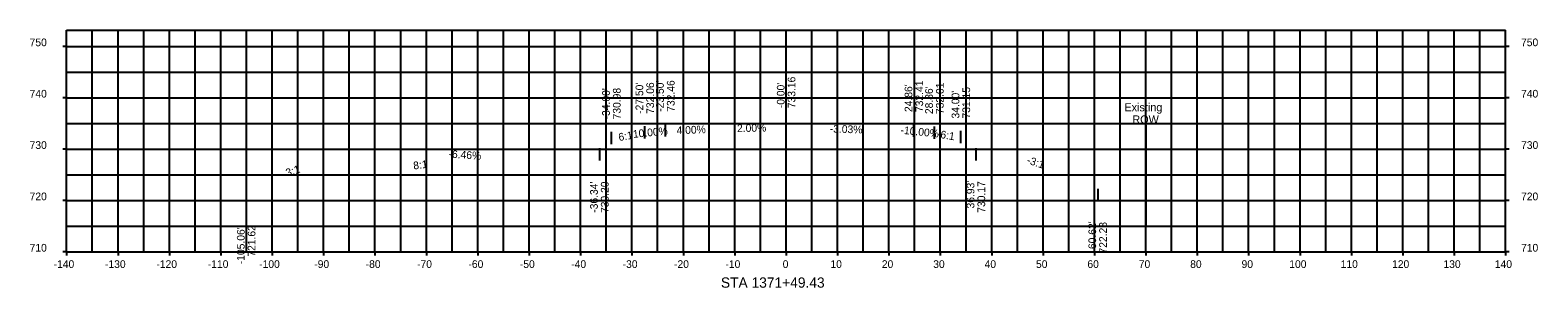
# Model space of a CAD drawing. Extents: x -147 to 146, y 703 to 753.
import ezdxf

# ---------------------------------------------------------------- set-up
doc = ezdxf.new("R2010")
doc.units = 0
for name, color, linetype in [('CorridorGraphics', 7, 'Continuous'), ('Text', 7, 'Continuous'), ('TL_DNC', 7, 'Continuous'), ('TL_PavementBtm', 7, 'Continuous'), ('TL_Set', 7, 'Continuous'), ('TL_SubbaseBtm', 7, 'Continuous')]:
    doc.layers.add(name, color=color, linetype=linetype)

msp = doc.modelspace()

# ---------------------------------------------------------------- linework, layer by layer
at = {"layer": 'CorridorGraphics'}
for p, q in [((-140, 753.16), (140, 753.16)), ((-140, 710), (-140, 753.16)), ((140, 710), (140, 753.16)), ((-140, 710), (140, 710))]:
    msp.add_line(p, q, dxfattribs=at)
at = {"layer": 'TL_DNC'}
for p, q in [((-135, 710), (-135, 753.16)), ((-125, 710), (-125, 753.16)), ((-115, 710), (-115, 753.16)), ((-105, 710), (-105, 753.16)), ((-95, 710), (-95, 753.16)), ((-85, 710), (-85, 753.16)), ((-75, 710), (-75, 753.16)), ((-65, 710), (-65, 753.16)), ((-55, 710), (-55, 753.16)), ((-45, 710), (-45, 753.16)), ((-35, 710), (-35, 753.16)), ((-25, 710), (-25, 753.16)), ((-15, 710), (-15, 753.16)), ((-5, 710), (-5, 753.16)), ((5, 710), (5, 753.16)), ((15, 710), (15, 753.16)), ((25, 710), (25, 753.16)), ((35, 710), (35, 753.16)), ((45, 710), (45, 753.16)), ((55, 710), (55, 753.16)), ((65, 710), (65, 753.16)), ((75, 710), (75, 753.16)), ((85, 710), (85, 753.16)), ((95, 710), (95, 753.16)), ((105, 710), (105, 753.16)), ((115, 710), (115, 753.16)), ((125, 710), (125, 753.16)), ((135, 710), (135, 753.16)), ((-140, 745), (140, 745)), ((-140, 735), (140, 735)), ((-140, 725), (140, 725)), ((-140, 715), (140, 715))]:
    msp.add_line(p, q, dxfattribs=at)
at = {"layer": 'TL_PavementBtm'}
for p, q in [((-27.5, 732.06), (-27.5, 734.46)), ((-23.5, 732.46), (-23.5, 734.86)), ((0, 733.16), (0, 735.56)), ((24.86, 732.41), (24.86, 734.81)), ((24.86, 732.41), (24.86, 734.81)), ((28.86, 732.01), (28.86, 734.41)), ((34, 731.15), (34, 733.55)), ((-34, 730.98), (-34, 733.38)), ((-36.34, 730.2), (-36.34, 727.8)), ((36.93, 730.17), (36.93, 727.77)), ((60.62, 722.28), (60.62, 719.88)), ((-105.06, 721.62), (-105.06, 719.22))]:
    msp.add_line(p, q, dxfattribs=at)
at = {"layer": 'TL_Set'}
msp.add_line((70.01, 734.64), (70.01, 714.95), dxfattribs=at)
at = {"layer": 'TL_SubbaseBtm'}
for p, q in [((-140, 710), (-140, 753.16)), ((-130, 710), (-130, 753.16)), ((-120, 710), (-120, 753.16)), ((-110, 710), (-110, 753.16)), ((-100, 710), (-100, 753.16)), ((-90, 710), (-90, 753.16)), ((-80, 710), (-80, 753.16)), ((-70, 710), (-70, 753.16)), ((-60, 710), (-60, 753.16)), ((-50, 710), (-50, 753.16)), ((-40, 710), (-40, 753.16)), ((-30, 710), (-30, 753.16)), ((-20, 710), (-20, 753.16)), ((-10, 710), (-10, 753.16)), ((0, 710), (0, 753.16)), ((10, 710), (10, 753.16)), ((20, 710), (20, 753.16)), ((30, 710), (30, 753.16)), ((40, 710), (40, 753.16)), ((50, 710), (50, 753.16)), ((60, 710), (60, 753.16)), ((70, 710), (70, 753.16)), ((80, 710), (80, 753.16)), ((90, 710), (90, 753.16)), ((100, 710), (100, 753.16)), ((110, 710), (110, 753.16)), ((120, 710), (120, 753.16)), ((130, 710), (130, 753.16)), ((140, 710), (140, 753.16)), ((-140, 750), (-140.72, 750)), ((-140, 750), (140, 750)), ((140.72, 750), (140, 750)), ((-140, 740), (-140.72, 740)), ((-140, 740), (140, 740)), ((140.72, 740), (140, 740)), ((-140, 730), (-140.72, 730)), ((-140, 730), (140, 730)), ((140.72, 730), (140, 730)), ((-140, 720), (-140.72, 720)), ((-140, 720), (140, 720)), ((140.72, 720), (140, 720)), ((-140, 710), (-140.72, 710)), ((-140, 710), (-140, 709.28)), ((-130, 710), (-130, 709.28)), ((-120, 710), (-120, 709.28)), ((-110, 710), (-110, 709.28)), ((-100, 710), (-100, 709.28)), ((-90, 710), (-90, 709.28)), ((-80, 710), (-80, 709.28)), ((-70, 710), (-70, 709.28)), ((-60, 710), (-60, 709.28)), ((-50, 710), (-50, 709.28)), ((-40, 710), (-40, 709.28)), ((-30, 710), (-30, 709.28)), ((-20, 710), (-20, 709.28)), ((-10, 710), (-10, 709.28)), ((0, 710), (0, 709.28)), ((10, 710), (10, 709.28)), ((20, 710), (20, 709.28)), ((30, 710), (30, 709.28)), ((40, 710), (40, 709.28)), ((50, 710), (50, 709.28)), ((60, 710), (60, 709.28)), ((70, 710), (70, 709.28)), ((80, 710), (80, 709.28)), ((90, 710), (90, 709.28)), ((100, 710), (100, 709.28)), ((110, 710), (110, 709.28)), ((120, 710), (120, 709.28)), ((130, 710), (130, 709.28)), ((140, 710), (140, 709.28)), ((140.72, 710), (140, 710))]:
    msp.add_line(p, q, dxfattribs=at)

# ---------------------------------------------------------------- texts
at = {"layer": 'Text'}
for s, height, p in [('750', 1.5, (-147.2, 750.03)), ('750', 1.5, (143, 750.03)), ('740', 1.5, (-147.2, 740.03)), ('740', 1.5, (143, 740.03)), ('730', 1.5, (-147.2, 730.03)), ('730', 1.5, (143, 730.03)), ('720', 1.5, (-147.2, 720.03)), ('720', 1.5, (143, 720.03)), ('710', 1.5, (-147.2, 710.03)), ('710', 1.5, (143, 710.03)), ('-140', 1.5, (-142.53, 706.85)), ('-130', 1.5, (-132.53, 706.85)), ('-120', 1.5, (-122.53, 706.85)), ('-110', 1.5, (-112.53, 706.85)), ('-100', 1.5, (-102.53, 706.85)), ('-90', 1.5, (-91.81, 706.85)), ('-80', 1.5, (-81.81, 706.85)), ('-70', 1.5, (-71.81, 706.85)), ('-60', 1.5, (-61.81, 706.85)), ('-50', 1.5, (-51.81, 706.85)), ('-40', 1.5, (-41.81, 706.85)), ('-30', 1.5, (-31.81, 706.85)), ('-20', 1.5, (-21.81, 706.85)), ('-10', 1.5, (-11.81, 706.85)), ('0', 1.5, (-0.67, 706.85)), ('10', 1.5, (8.62, 706.85)), ('20', 1.5, (18.62, 706.85)), ('30', 1.5, (28.62, 706.85)), ('40', 1.5, (38.62, 706.85)), ('50', 1.5, (48.62, 706.85)), ('60', 1.5, (58.62, 706.85)), ('70', 1.5, (68.62, 706.85)), ('80', 1.5, (78.62, 706.85)), ('90', 1.5, (88.62, 706.85)), ('100', 1.5, (97.9, 706.85)), ('110', 1.5, (107.9, 706.85)), ('120', 1.5, (117.9, 706.85)), ('130', 1.5, (127.9, 706.85)), ('140', 1.5, (137.9, 706.85)), ('STA 1371+49.43', 2.004, (-12.69, 703))]:
    msp.add_text(s, height=height, dxfattribs=at).set_placement(p)
at = {"layer": 'TL_PavementBtm'}
for s, rotation, p in [("-27.50'", 90, (-27.8, 736.86)), ('732.06', 90, (-25.7, 736.86)), ("-23.50'", 90, (-23.8, 737.26)), ('732.46', 90, (-21.7, 737.26)), ("-0.00'", 90, (-0.3, 737.96)), ('733.16', 90, (1.8, 737.96)), ("24.86'", 90, (24.56, 737.21)), ("24.86'", 90, (24.56, 737.21)), ('732.41', 90, (26.66, 737.21)), ('732.41', 90, (26.66, 737.21)), ('732.01', 90, (30.66, 736.81)), ("-34.00'", 90, (-34.3, 735.78)), ('730.98', 90, (-32.2, 735.78)), ("28.86'", 90, (28.56, 736.81)), ("34.00'", 90, (33.7, 735.95)), ('731.15', 90, (35.8, 735.95)), ('6:1', 9.4642, (-32.5, 731.56)), ('10.00%', 5.7106, (-29.74, 732.17)), ('4.00%', 2.2906, (-21.29, 732.88)), ('2.00%', 1.1458, (-9.54, 733.3)), ('-3.03%', 358.2618, (8.47, 733.23)), ('-10.00%', 354.2894, (22.21, 733)), ('-6:1', 350.5358, (29.27, 732.27)), ('8:1', 7.1191, (-72.46, 726.02)), ('-6.46%', 356.3052, (-65.72, 728.34)), ('-3:1', 341.5651, (46.7, 727.25)), ('3:1', 18.4365, (-97.08, 724.61)), ("-36.34'", 90, (-36.64, 717.6)), ('730.20', 90, (-34.54, 717.55)), ("36.93'", 90, (36.63, 718.43)), ('730.17', 90, (38.73, 717.6)), ("60.62'", 90, (60.32, 710.53)), ("-105.06'", 90, (-105.36, 707.58)), ('721.62', 90, (-103.26, 709.05)), ('722.28', 90, (62.42, 709.66))]:
    msp.add_text(s, height=1.5, rotation=rotation, dxfattribs=at).set_placement(p)
at = {"layer": 'TL_Set'}
for s, p in [('Existing', (65.83, 737.35)), ('ROW', (67.37, 734.98))]:
    msp.add_text(s, height=1.575, dxfattribs=at).set_placement(p)

doc.saveas('drawing.dxf')
